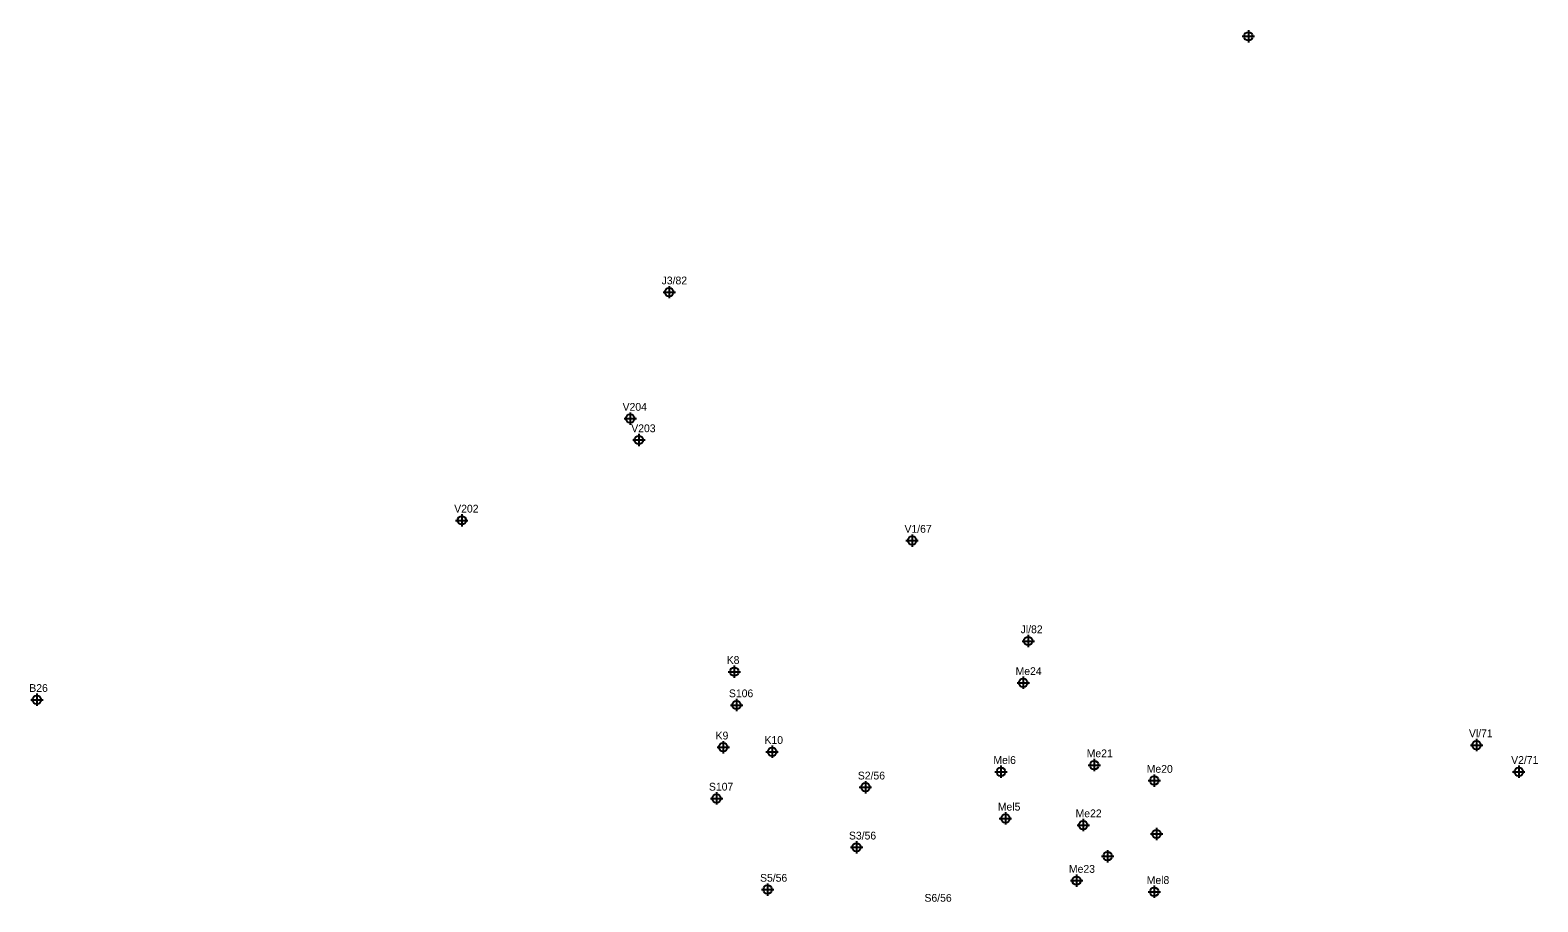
# Model space of a CAD drawing. Extents: x -597749 to -595427, y -1168718 to -1166900.
# Drawn here: x -597749 to -597070, y -1168089 to -1167696 of the extents above; entities that cross this region are included whole.
import ezdxf

# ---------------------------------------------------------------- set-up
doc = ezdxf.new("R2010")
doc.units = 0
doc.layers.add('13_archivní průzkum', color=7, linetype='Continuous')

# ---------------------------------------------------------------- blocks, each defined once
blk = doc.blocks.new('IG vrt OK')
for p, q in [((0, 0.198), (0, -0.198)), ((-0.198, 0), (0.198, 0))]:
    blk.add_line(p, q)
blk.add_circle((0, 0), 0.138)

msp = doc.modelspace()

# ---------------------------------------------------------------- block references
at = {"layer": '13_archivní průzkum', "xscale": 13.9855072, "yscale": 13.9855072}
for p in [(-597200.68, -1167699.14), (-597461.29, -1167814.25), (-597478.86, -1167871.11), (-597474.96, -1167880.76), (-597554.63, -1167916.91), (-597352, -1167926), (-597299.74, -1167971.19), (-597432, -1167985), (-597302, -1167990), (-597745.85, -1167997.61), (-597431, -1168000), (-597437, -1168019), (-597098, -1168018), (-597415, -1168021), (-597270, -1168027), (-597312, -1168030), (-597079, -1168030), (-597373, -1168037), (-597243, -1168034), (-597440, -1168042), (-597310, -1168051), (-597275, -1168054), (-597242, -1168058), (-597377, -1168064), (-597264, -1168068), (-597278, -1168079), (-597417, -1168083), (-597243, -1168084)]:
    msp.add_blockref('IG vrt OK', p, dxfattribs=at)

# ---------------------------------------------------------------- texts
at = {"layer": '13_archivní průzkum'}
for s, p in [('J3/82', (-597464.7, -1167810.74)), ('V204', (-597482.27, -1167867.6)), ('V203', (-597478.37, -1167877.25)), ('V202', (-597558.04, -1167913.4)), ('V1/67', (-597355.41, -1167922.49)), ('Jl/82', (-597303.15, -1167967.68)), ('K8', (-597435.41, -1167981.49)), ('Me24', (-597305.41, -1167986.49)), ('B26', (-597749.26, -1167994.1)), ('S106', (-597434.41, -1167996.49)), ('K9', (-597440.41, -1168015.49)), ('K10', (-597418.41, -1168017.49)), ('Vl/71', (-597101.41, -1168014.49)), ('Mel6', (-597315.41, -1168026.49)), ('Me21', (-597273.41, -1168023.49)), ('V2/71', (-597082.41, -1168026.49)), ('S2/56', (-597376.41, -1168033.49)), ('Me20', (-597246.41, -1168030.49)), ('S107', (-597443.41, -1168038.49)), ('Mel5', (-597313.41, -1168047.49)), ('Me22', (-597278.41, -1168050.49)), ('S3/56', (-597380.41, -1168060.49)), ('S5/56', (-597420.41, -1168079.49)), ('Me23', (-597281.41, -1168075.49)), ('Mel8', (-597246.41, -1168080.49)), ('S6/56', (-597346.41, -1168088.49))]:
    msp.add_text(s, height=3.5, dxfattribs=at).set_placement(p)

doc.saveas('drawing.dxf')
